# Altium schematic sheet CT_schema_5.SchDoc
size 309 x 315 mm
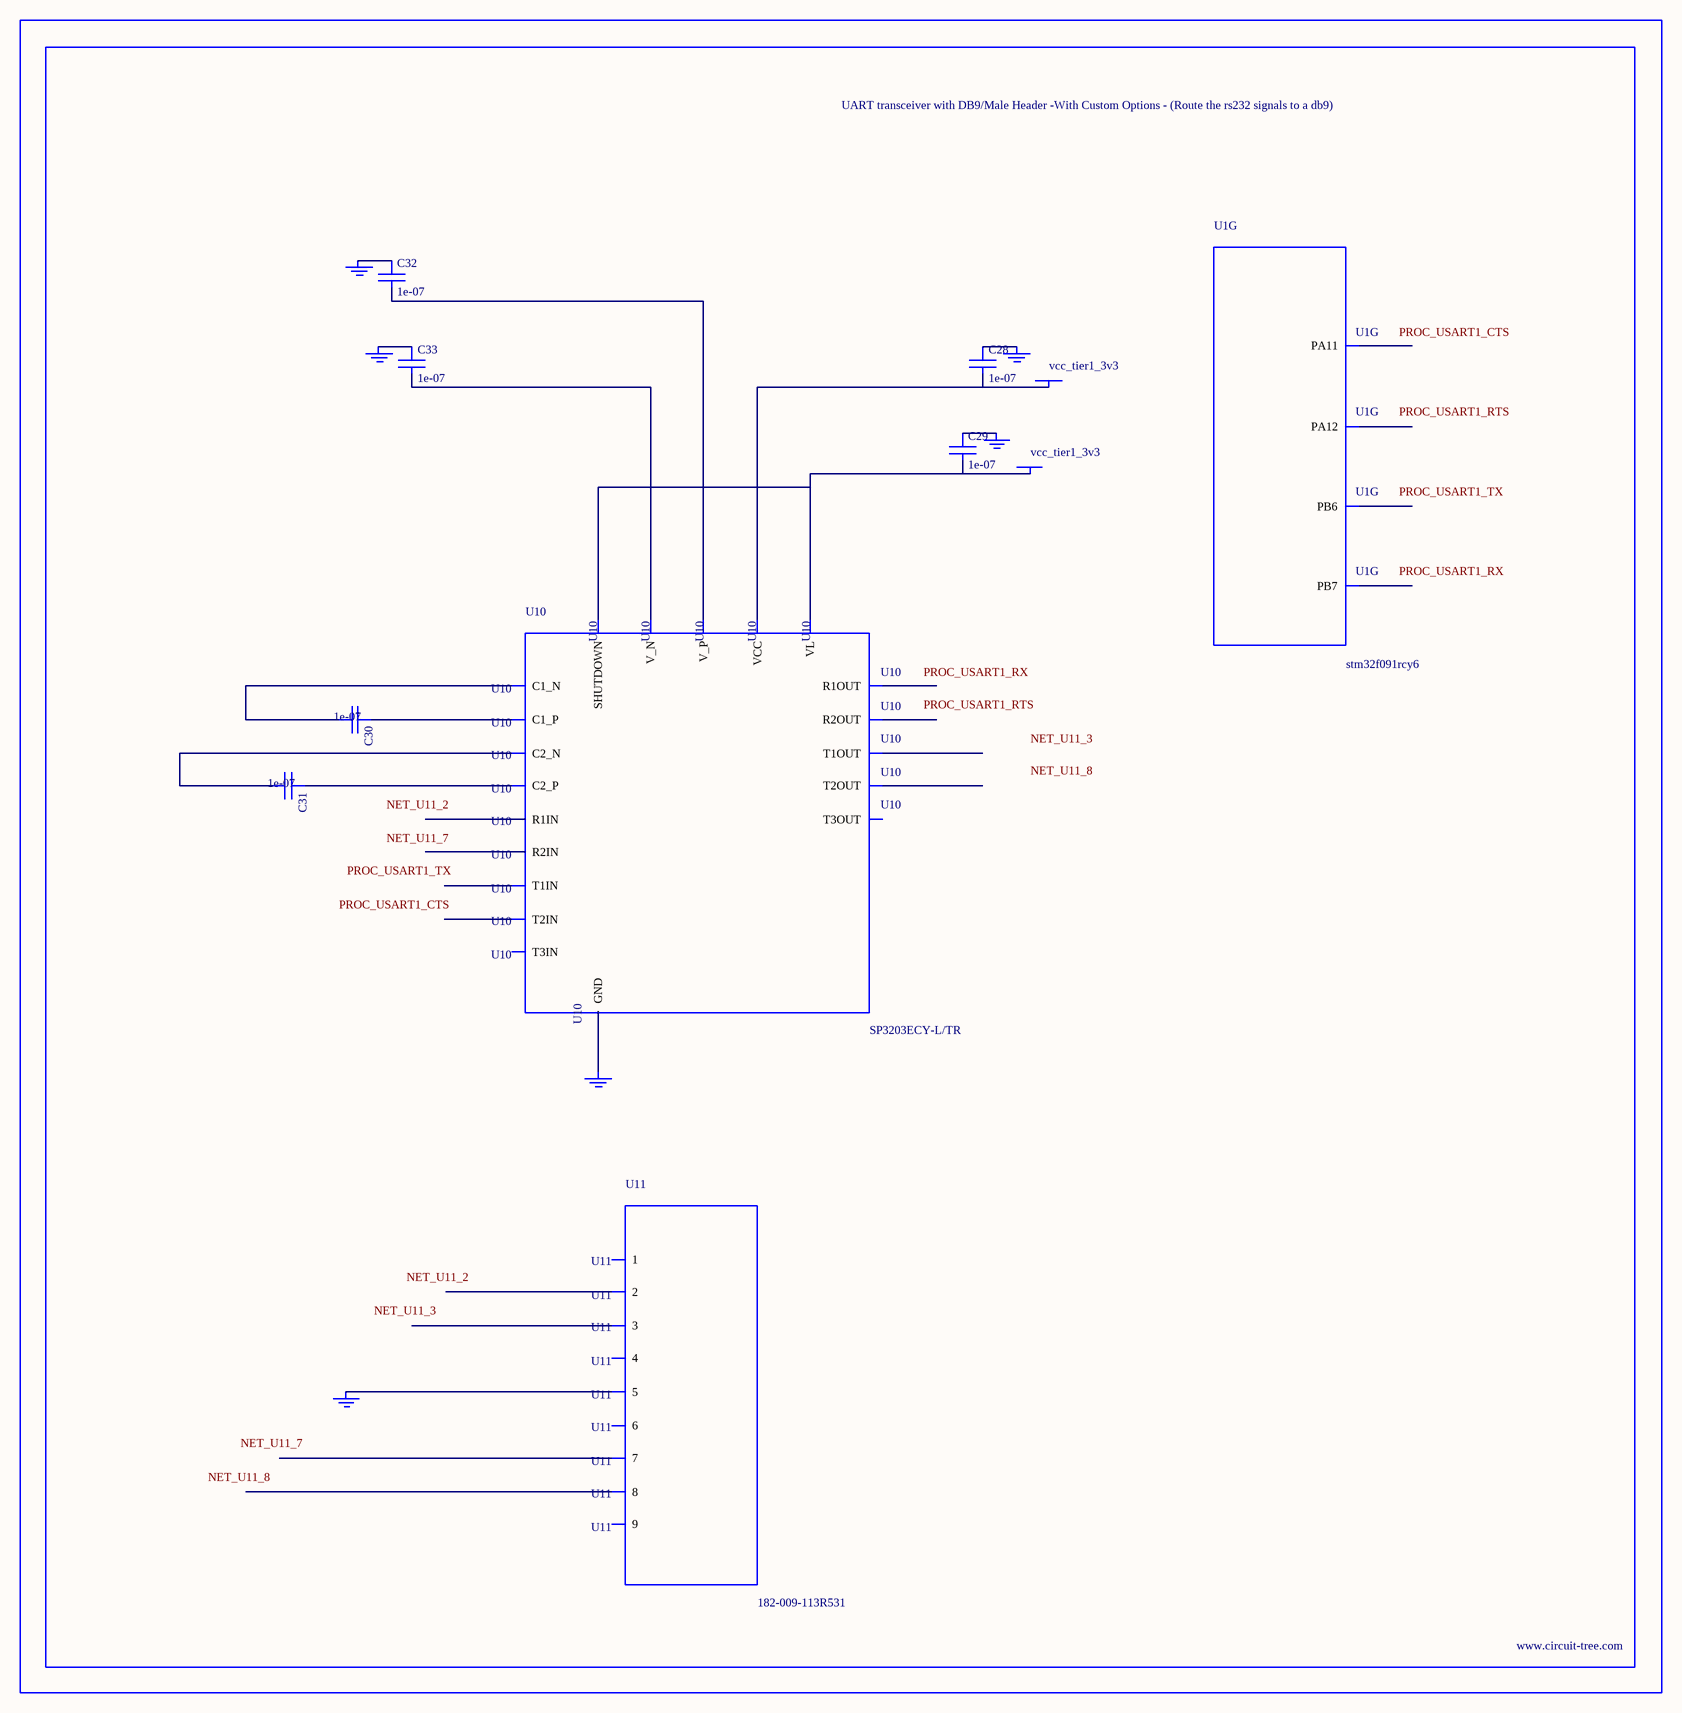
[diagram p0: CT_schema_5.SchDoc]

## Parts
BORDER4  (no value)
C28  1e-07  [C0402]
C29  1e-07  [C0402]
C30  1e-07  [C0402]
C31  1e-07  [C0402]
C32  1e-07  [C0402]
C33  1e-07  [C0402]
GND_INSTANCE_4_0  (no value)
GND_INSTANCE_4_1  (no value)
GND_INSTANCE_4_2  (no value)
GND_INSTANCE_4_3  (no value)
GND_INSTANCE_4_4  (no value)
GND_INSTANCE_4_5  (no value)
POWER_INSTANCE_4_0  vcc_tier1_3v3
POWER_INSTANCE_4_1  vcc_tier1_3v3
U1  stm32f091rcy6  [WLCSP64]  (part G of 8)
U10  SP3203ECY-L/TR  [TSSOP20-I]
U11  182-009-113R531  [182-009-MALE]

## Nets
NetC28_1: C28.1 GND_INSTANCE_4_3.0(GND)
NetC28_2: C28.2 POWER_INSTANCE_4_1.0(PWR) U10.19(VCC)
NetC29_1: C29.1 GND_INSTANCE_4_2.0(GND)
NetC29_2: C29.2 POWER_INSTANCE_4_0.0(PWR) U10.12(VL) U10.20(SHUTDOWN)
NetC30_1: C30.1 U10.1(C1_P)
NetC30_2: C30.2 U10.3(C1_N)
NetC31_1: C31.1 U10.4(C2_P)
NetC31_2: C31.2 U10.5(C2_N)
NetC32_1: C32.1 GND_INSTANCE_4_0.0(GND)
NetC32_2: C32.2 U10.2(V_P)
NetC33_1: C33.1 GND_INSTANCE_4_1.0(GND)
NetC33_2: C33.2 U10.6(V_N)
NetGND_INSTANCE_4_4_0: GND_INSTANCE_4_4.0(GND) U10.18(GND)
NetGND_INSTANCE_4_5_0: GND_INSTANCE_4_5.0(GND) U11.5

Not connected (* = marked no-connect by the designer): U1 A5(PB6) B1(PA12) B5(PB7) D3(PA11); U10 7(T1IN) 8(T2IN) 9(T3IN) 10(R2OUT) 11(R1OUT) 13(R2IN) 14(R1IN) 15(T3OUT) 16(T2OUT) 17(T1OUT); U11 1 2 3 4 6 7 8 9

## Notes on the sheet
- Labels drawn without touching a wire or pin: NET_U11_2, NET_U11_3, NET_U11_7, NET_U11_8, PROC_USART1_CTS, PROC_USART1_RTS, PROC_USART1_RX, PROC_USART1_TX

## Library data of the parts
BORDER4 = BORDER_PAGE4
C28-C33 = C0402C104K3RACTU
GND_INSTANCE_4_0-GND_INSTANCE_4_5 = GND
POWER_INSTANCE_4_0 POWER_INSTANCE_4_1 = PWR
